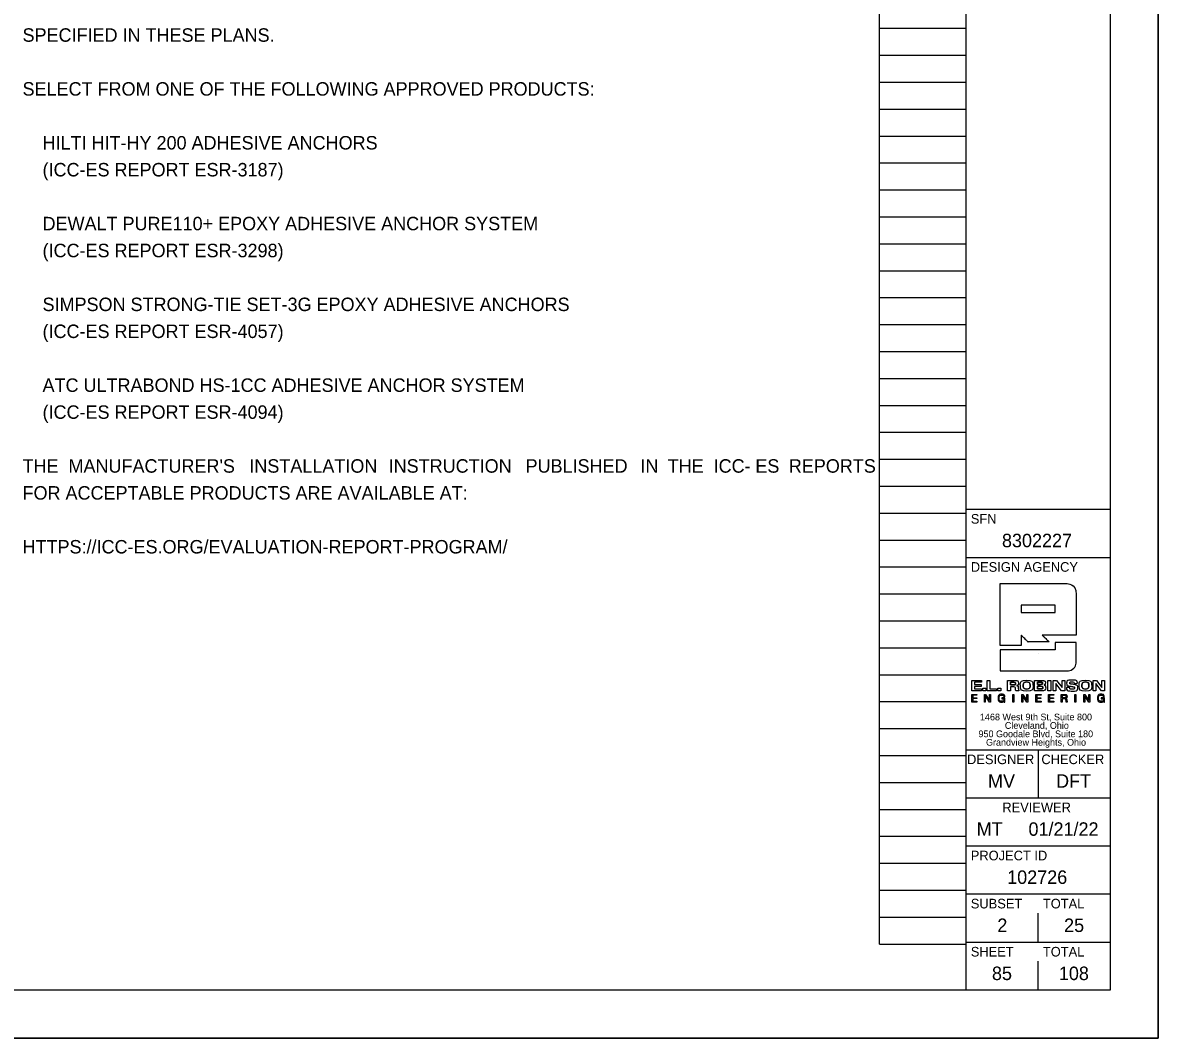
# Model space of a CAD drawing. Extents: x 0 to 34, y 0 to 22.
# Drawn here: x 22.19 to 34, y 0 to 10.56 of the extents above; entities that cross this region are included whole.
import ezdxf

# ---------------------------------------------------------------- set-up
doc = ezdxf.new("R2010")
doc.units = 0
for name, color, linetype in [('SC_Scratch1', 7, 'Continuous'), ('SH_Border', 7, 'Continuous'), ('SH_Cut_Line', 7, 'Continuous'), ('SH_Data', 7, 'Continuous'), ('SH_Text', 7, 'Continuous')]:
    doc.layers.add(name, color=color, linetype=linetype)

msp = doc.modelspace()

# ---------------------------------------------------------------- linework, layer by layer
at = {"layer": 'SC_Scratch1'}
for p, q in [((31.1, 0.98), (31.1, 21.14)), ((32, 0.98), (32, 21.14)), ((31.1, 10.5), (32, 10.5)), ((31.1, 10.22), (32, 10.22)), ((31.1, 9.94), (32, 9.94)), ((31.1, 9.66), (32, 9.66)), ((31.1, 9.38), (32, 9.38)), ((31.1, 9.1), (32, 9.1)), ((31.1, 8.82), (32, 8.82)), ((31.1, 8.54), (32, 8.54)), ((31.1, 8.26), (32, 8.26)), ((31.1, 7.98), (32, 7.98)), ((31.1, 7.7), (32, 7.7)), ((31.1, 7.42), (32, 7.42)), ((31.1, 7.14), (32, 7.14)), ((31.1, 6.86), (32, 6.86)), ((31.1, 6.58), (32, 6.58)), ((31.1, 6.3), (32, 6.3)), ((31.1, 6.02), (32, 6.02)), ((31.1, 5.74), (32, 5.74)), ((31.1, 5.46), (32, 5.46)), ((31.1, 5.18), (32, 5.18)), ((31.1, 4.9), (32, 4.9)), ((31.1, 4.62), (32, 4.62)), ((31.1, 4.34), (32, 4.34)), ((31.1, 4.06), (32, 4.06)), ((31.1, 3.78), (32, 3.78)), ((31.1, 3.5), (32, 3.5)), ((31.1, 3.22), (32, 3.22)), ((31.1, 2.94), (32, 2.94)), ((31.1, 2.66), (32, 2.66)), ((31.1, 2.38), (32, 2.38)), ((31.1, 2.1), (32, 2.1)), ((31.1, 1.82), (32, 1.82)), ((31.1, 1.54), (32, 1.54)), ((31.1, 1.26), (32, 1.26)), ((31.1, 0.98), (32, 0.98))]:
    msp.add_line(p, q, dxfattribs=at)
msp.add_lwpolyline([(0, 22), (34, 22), (34, 0), (0, 0)], close=True, dxfattribs=at)
at = {"layer": 'SH_Border'}
for p, q in [((32, 0.5), (32, 21.5)), ((32, 5.5), (33.5, 5.5)), ((32, 5), (33.5, 5)), ((32, 3), (33.5, 3)), ((32.75, 3), (32.75, 2.5)), ((32, 2.5), (33.5, 2.5)), ((32, 2), (33.5, 2)), ((32, 1.5), (33.5, 1.5)), ((32, 1), (33.5, 1))]:
    msp.add_line(p, q, dxfattribs=at)
msp.add_lwpolyline([(1.5, 21.5), (33.5, 21.5), (33.5, 0.5), (1.5, 0.5)], close=True, dxfattribs=at)
at = {"layer": 'SH_Cut_Line'}
msp.add_lwpolyline([(0, 0), (34, 0), (34, 22), (0, 22)], close=True, dxfattribs=at)
at = {"layer": 'SH_Data'}
for p, q in [((32.929, 4.503), (32.574, 4.503)), ((32.574, 4.503), (32.574, 4.425)), ((32.929, 4.425), (32.929, 4.503)), ((32.574, 4.425), (32.929, 4.425)), ((32.75, 4), (32.75, 4)), ((32.463, 3.701), (32.463, 3.673)), ((32.743, 3.702), (32.743, 3.678)), ((32.743, 3.659), (32.743, 3.633)), ((33.001, 3.566), (33.001, 3.539)), ((33.001, 3.539), (33.023, 3.539)), ((32.75, 1), (32.75, 1.3)), ((32.75, 0.5), (32.75, 0.8)), ((32.375, 0.675), (32.375, 0.675))]:
    msp.add_line(p, q, dxfattribs=at)
for points in [[(32.06, 3.721), (32.161, 3.721), (32.161, 3.701), (32.089, 3.701), (32.089, 3.678), (32.158, 3.678), (32.158, 3.658), (32.089, 3.658), (32.089, 3.633), (32.162, 3.633), (32.162, 3.613), (32.06, 3.613), (32.06, 3.721)], [(32.22, 3.721), (32.249, 3.721), (32.249, 3.634), (32.316, 3.634), (32.316, 3.613), (32.22, 3.613), (32.22, 3.721)], [(32.851, 3.721), (32.881, 3.721), (32.881, 3.613), (32.851, 3.613), (32.851, 3.721)], [(32.999, 3.721), (33.027, 3.721), (33.027, 3.613), (32.995, 3.613), (32.936, 3.689), (32.936, 3.689), (32.936, 3.613), (32.907, 3.613), (32.907, 3.721), (32.941, 3.721), (32.999, 3.646), (32.999, 3.646), (32.999, 3.721)], [(33.413, 3.721), (33.442, 3.721), (33.442, 3.613), (33.41, 3.613), (33.35, 3.689), (33.35, 3.689), (33.35, 3.613), (33.321, 3.613), (33.321, 3.721), (33.356, 3.721), (33.413, 3.646), (33.413, 3.646), (33.413, 3.721)], [(32.059, 3.575), (32.114, 3.575), (32.114, 3.566), (32.07, 3.566), (32.07, 3.541), (32.111, 3.541), (32.111, 3.532), (32.07, 3.532), (32.07, 3.505), (32.114, 3.505), (32.114, 3.496), (32.059, 3.496), (32.059, 3.575)], [(32.175, 3.639), (32.205, 3.639), (32.205, 3.613), (32.175, 3.613), (32.175, 3.639)], [(32.191, 3.575), (32.203, 3.575), (32.244, 3.511), (32.244, 3.511), (32.244, 3.575), (32.254, 3.575), (32.254, 3.496), (32.243, 3.496), (32.202, 3.559), (32.201, 3.559), (32.201, 3.496), (32.191, 3.496), (32.191, 3.575)], [(32.331, 3.639), (32.361, 3.639), (32.361, 3.613), (32.331, 3.613), (32.331, 3.639)], [(32.487, 3.575), (32.498, 3.575), (32.498, 3.496), (32.487, 3.496), (32.487, 3.575)], [(32.581, 3.575), (32.592, 3.575), (32.633, 3.511), (32.633, 3.511), (32.633, 3.575), (32.643, 3.575), (32.643, 3.496), (32.632, 3.496), (32.591, 3.559), (32.591, 3.559), (32.591, 3.496), (32.581, 3.496), (32.581, 3.575)], [(32.726, 3.575), (32.781, 3.575), (32.781, 3.566), (32.737, 3.566), (32.737, 3.541), (32.778, 3.541), (32.778, 3.532), (32.737, 3.532), (32.737, 3.505), (32.781, 3.505), (32.781, 3.496), (32.726, 3.496), (32.726, 3.575)], [(32.859, 3.575), (32.913, 3.575), (32.913, 3.566), (32.869, 3.566), (32.869, 3.541), (32.91, 3.541), (32.91, 3.532), (32.869, 3.532), (32.869, 3.505), (32.913, 3.505), (32.913, 3.496), (32.859, 3.496), (32.859, 3.575)], [(33.133, 3.575), (33.143, 3.575), (33.143, 3.496), (33.133, 3.496), (33.133, 3.575)], [(33.226, 3.575), (33.237, 3.575), (33.279, 3.511), (33.279, 3.511), (33.279, 3.575), (33.289, 3.575), (33.289, 3.496), (33.277, 3.496), (33.236, 3.559), (33.236, 3.559), (33.236, 3.496), (33.226, 3.496), (33.226, 3.575)]]:
    msp.add_lwpolyline(points, dxfattribs=at)
for points, degree in [([(32.356, 4.083), (32.356, 4.086), (32.356, 4.724), (32.356, 4.727)], 2), ([(32.356, 4.727), (32.36, 4.727), (33.03, 4.727), (33.034, 4.727), (33.096, 4.727), (33.147, 4.677), (33.147, 4.614)], 3), ([(33.147, 4.614), (33.147, 4.612), (33.147, 4.194), (33.147, 4.192)], 2), ([(32.645, 4.121), (32.645, 4.121), (32.574, 4.191), (32.574, 4.192)], 2), ([(32.574, 4.192), (32.574, 4.191), (32.574, 4.083), (32.574, 4.083)], 2), ([(33.147, 4.192), (33.145, 4.192), (32.795, 4.192), (32.793, 4.192)], 2), ([(32.793, 4.192), (32.793, 4.191), (32.866, 4.121), (32.866, 4.121)], 2), ([(32.929, 4.115), (32.929, 4.115), (33.147, 4.115), (33.147, 4.115), (33.147, 4.115), (33.147, 3.933), (33.147, 3.933), (33.147, 3.87), (33.096, 3.82), (33.034, 3.82), (33.034, 3.82), (32.356, 3.82), (32.356, 3.82), (32.356, 3.82), (32.356, 4.037), (32.356, 4.037), (32.356, 4.037), (32.929, 4.037), (32.929, 4.037), (32.929, 4.037), (32.929, 4.115), (32.929, 4.115)], 3), ([(32.574, 4.083), (32.573, 4.083), (32.357, 4.083), (32.356, 4.083)], 2), ([(32.866, 4.121), (32.865, 4.121), (32.646, 4.121), (32.645, 4.121)], 2), ([(32.433, 3.613), (32.433, 3.613), (32.433, 3.721), (32.433, 3.721)], 2), ([(32.433, 3.721), (32.433, 3.721), (32.512, 3.721), (32.512, 3.721), (32.542, 3.721), (32.545, 3.703), (32.546, 3.692)], 3), ([(32.463, 3.673), (32.463, 3.673), (32.502, 3.673), (32.502, 3.673), (32.508, 3.673), (32.516, 3.677), (32.516, 3.687), (32.516, 3.698), (32.507, 3.701), (32.5, 3.701), (32.5, 3.701), (32.463, 3.701), (32.463, 3.701), (32.463, 3.701), (32.463, 3.673), (32.463, 3.673)], 3), ([(32.463, 3.673), (32.476, 3.673), (32.489, 3.673), (32.508, 3.673), (32.516, 3.677), (32.516, 3.698), (32.507, 3.701), (32.488, 3.701), (32.475, 3.701), (32.463, 3.701)], 3), ([(32.546, 3.692), (32.544, 3.679), (32.542, 3.67), (32.53, 3.666)], 2), ([(32.53, 3.666), (32.53, 3.666), (32.53, 3.665), (32.53, 3.665)], 2), ([(32.53, 3.665), (32.543, 3.663), (32.544, 3.647), (32.544, 3.636)], 2), ([(32.631, 3.61), (32.573, 3.61), (32.567, 3.645), (32.565, 3.667), (32.564, 3.69), (32.573, 3.724), (32.631, 3.724)], 3), ([(32.631, 3.63), (32.658, 3.63), (32.667, 3.65), (32.667, 3.667), (32.667, 3.684), (32.658, 3.704), (32.631, 3.704), (32.604, 3.704), (32.595, 3.684), (32.595, 3.667), (32.595, 3.65), (32.604, 3.63), (32.631, 3.63)], 3), ([(32.631, 3.704), (32.604, 3.704), (32.595, 3.684), (32.595, 3.667), (32.595, 3.65), (32.604, 3.63), (32.631, 3.63)], 3), ([(32.631, 3.724), (32.69, 3.724), (32.695, 3.689), (32.697, 3.667), (32.699, 3.644), (32.69, 3.61), (32.631, 3.61)], 3), ([(32.631, 3.63), (32.658, 3.63), (32.667, 3.65), (32.667, 3.667), (32.667, 3.684), (32.658, 3.704), (32.631, 3.704)], 3), ([(32.714, 3.613), (32.714, 3.613), (32.714, 3.721), (32.714, 3.721)], 2), ([(32.714, 3.721), (32.714, 3.721), (32.795, 3.721), (32.795, 3.721)], 2), ([(32.743, 3.678), (32.743, 3.678), (32.784, 3.678), (32.784, 3.678), (32.791, 3.678), (32.796, 3.682), (32.796, 3.69), (32.796, 3.697), (32.793, 3.702), (32.78, 3.702), (32.78, 3.702), (32.743, 3.702), (32.743, 3.702), (32.743, 3.702), (32.743, 3.678), (32.743, 3.678)], 3), ([(32.743, 3.678), (32.757, 3.678), (32.771, 3.678), (32.791, 3.681), (32.791, 3.683), (32.792, 3.697), (32.793, 3.702), (32.768, 3.702), (32.756, 3.702), (32.743, 3.702)], 3), ([(32.795, 3.721), (32.81, 3.718), (32.826, 3.714), (32.826, 3.694)], 2), ([(32.826, 3.694), (32.824, 3.686), (32.822, 3.675), (32.812, 3.672)], 2), ([(32.812, 3.672), (32.812, 3.672), (32.812, 3.672), (32.812, 3.672)], 2), ([(32.812, 3.672), (32.824, 3.67), (32.827, 3.656), (32.829, 3.645)], 2), ([(33.126, 3.69), (33.124, 3.704), (33.111, 3.706), (33.099, 3.706), (33.087, 3.706), (33.079, 3.7), (33.079, 3.693), (33.079, 3.687), (33.084, 3.684), (33.091, 3.683), (33.091, 3.683), (33.128, 3.677), (33.128, 3.677), (33.148, 3.673), (33.163, 3.666), (33.163, 3.646), (33.163, 3.626), (33.149, 3.61), (33.107, 3.61), (33.08, 3.61), (33.046, 3.613), (33.045, 3.647), (33.045, 3.647), (33.079, 3.647), (33.079, 3.647), (33.079, 3.632), (33.094, 3.629), (33.107, 3.629), (33.121, 3.629), (33.13, 3.634), (33.13, 3.643), (33.13, 3.651), (33.123, 3.654), (33.112, 3.655), (33.112, 3.655), (33.085, 3.66), (33.085, 3.66), (33.066, 3.662), (33.047, 3.668), (33.047, 3.69), (33.047, 3.715), (33.067, 3.724), (33.101, 3.724), (33.124, 3.724), (33.157, 3.721), (33.159, 3.69), (33.159, 3.69), (33.126, 3.69), (33.126, 3.69)], 3), ([(33.242, 3.61), (33.183, 3.61), (33.178, 3.645), (33.176, 3.667), (33.174, 3.69), (33.183, 3.724), (33.242, 3.724)], 3), ([(33.242, 3.63), (33.269, 3.63), (33.278, 3.65), (33.278, 3.667), (33.278, 3.684), (33.269, 3.704), (33.242, 3.704), (33.215, 3.704), (33.205, 3.684), (33.205, 3.667), (33.205, 3.65), (33.215, 3.63), (33.242, 3.63)], 3), ([(33.242, 3.704), (33.215, 3.704), (33.205, 3.684), (33.205, 3.667), (33.205, 3.65), (33.215, 3.63), (33.242, 3.63)], 3), ([(33.242, 3.724), (33.3, 3.724), (33.306, 3.689), (33.308, 3.667), (33.309, 3.644), (33.3, 3.61), (33.242, 3.61)], 3), ([(33.242, 3.63), (33.269, 3.63), (33.278, 3.65), (33.278, 3.667), (33.278, 3.684), (33.269, 3.704), (33.242, 3.704)], 3), ([(32.396, 3.506), (32.39, 3.498), (32.38, 3.494), (32.37, 3.494), (32.347, 3.494), (32.333, 3.514), (32.333, 3.534), (32.333, 3.557), (32.346, 3.577), (32.37, 3.577), (32.388, 3.577), (32.401, 3.569), (32.404, 3.551), (32.404, 3.551), (32.394, 3.551), (32.394, 3.551), (32.392, 3.562), (32.382, 3.568), (32.37, 3.568), (32.351, 3.568), (32.344, 3.551), (32.344, 3.534), (32.344, 3.518), (32.353, 3.503), (32.37, 3.503), (32.387, 3.503), (32.396, 3.515), (32.396, 3.529), (32.396, 3.529), (32.371, 3.529), (32.371, 3.529), (32.371, 3.529), (32.371, 3.538), (32.371, 3.538), (32.371, 3.538), (32.405, 3.538), (32.405, 3.538), (32.405, 3.538), (32.405, 3.496), (32.405, 3.496), (32.405, 3.496), (32.398, 3.496), (32.398, 3.496), (32.398, 3.496), (32.396, 3.506), (32.396, 3.506)], 3), ([(32.463, 3.613), (32.462, 3.613), (32.433, 3.613), (32.433, 3.613)], 2), ([(32.499, 3.653), (32.499, 3.653), (32.463, 3.653), (32.463, 3.653)], 2), ([(32.463, 3.653), (32.463, 3.652), (32.463, 3.613), (32.463, 3.613)], 2), ([(32.518, 3.613), (32.516, 3.618), (32.516, 3.622), (32.516, 3.634), (32.515, 3.649), (32.508, 3.65), (32.499, 3.653)], 3), ([(32.55, 3.613), (32.55, 3.613), (32.518, 3.613), (32.518, 3.613)], 2), ([(32.544, 3.636), (32.544, 3.631), (32.548, 3.619), (32.55, 3.613)], 2), ([(32.829, 3.645), (32.827, 3.632), (32.824, 3.613), (32.791, 3.613), (32.791, 3.613), (32.714, 3.613), (32.714, 3.613)], 3), ([(32.743, 3.633), (32.743, 3.633), (32.787, 3.633), (32.787, 3.633), (32.796, 3.633), (32.8, 3.639), (32.8, 3.646), (32.8, 3.655), (32.794, 3.659), (32.784, 3.659), (32.784, 3.659), (32.743, 3.659), (32.743, 3.659), (32.743, 3.659), (32.743, 3.633), (32.743, 3.633)], 3), ([(32.743, 3.633), (32.758, 3.633), (32.772, 3.633), (32.796, 3.633), (32.8, 3.639), (32.8, 3.655), (32.794, 3.659), (32.77, 3.659), (32.757, 3.659), (32.743, 3.659)], 3), ([(32.991, 3.575), (32.991, 3.575), (33.027, 3.575), (33.028, 3.575), (33.042, 3.575), (33.051, 3.567), (33.051, 3.554)], 3), ([(32.991, 3.496), (32.991, 3.497), (32.991, 3.574), (32.991, 3.575)], 2), ([(33.023, 3.539), (33.033, 3.539), (33.041, 3.541), (33.041, 3.552), (33.041, 3.56), (33.037, 3.566), (33.027, 3.566), (33.027, 3.566), (33.001, 3.566), (33.001, 3.566), (33.001, 3.566), (33.001, 3.539), (33.001, 3.539), (33.001, 3.539), (33.023, 3.539), (33.023, 3.539)], 3), ([(33.023, 3.539), (33.033, 3.539), (33.041, 3.541), (33.041, 3.56), (33.037, 3.566), (33.018, 3.566), (33.01, 3.566), (33.001, 3.566)], 3), ([(33.051, 3.554), (33.049, 3.545), (33.047, 3.537), (33.038, 3.534)], 2), ([(33.43, 3.506), (33.424, 3.498), (33.414, 3.494), (33.405, 3.494), (33.382, 3.494), (33.368, 3.514), (33.368, 3.534), (33.368, 3.557), (33.38, 3.577), (33.405, 3.577), (33.422, 3.577), (33.436, 3.569), (33.439, 3.551), (33.439, 3.551), (33.429, 3.551), (33.429, 3.551), (33.426, 3.562), (33.417, 3.568), (33.405, 3.568), (33.386, 3.568), (33.378, 3.551), (33.378, 3.534), (33.378, 3.518), (33.388, 3.503), (33.405, 3.503), (33.421, 3.503), (33.431, 3.515), (33.43, 3.529), (33.43, 3.529), (33.405, 3.529), (33.405, 3.529), (33.405, 3.529), (33.405, 3.538), (33.405, 3.538), (33.405, 3.538), (33.44, 3.538), (33.44, 3.538), (33.44, 3.538), (33.44, 3.496), (33.44, 3.496), (33.44, 3.496), (33.433, 3.496), (33.433, 3.496), (33.433, 3.496), (33.43, 3.506), (33.43, 3.506)], 3), ([(33.001, 3.496), (33.001, 3.496), (32.991, 3.496), (32.991, 3.496)], 2), ([(33.04, 3.516), (33.038, 3.523), (33.037, 3.53), (33.027, 3.53), (33.027, 3.53), (33.001, 3.53), (33.001, 3.53)], 3), ([(33.001, 3.53), (33.001, 3.53), (33.001, 3.496), (33.001, 3.496)], 2), ([(33.038, 3.534), (33.038, 3.534), (33.038, 3.534), (33.038, 3.534)], 2), ([(33.038, 3.534), (33.044, 3.529), (33.047, 3.525), (33.048, 3.518)], 2), ([(33.043, 3.496), (33.042, 3.5), (33.041, 3.508), (33.04, 3.516)], 2), ([(33.054, 3.496), (33.054, 3.496), (33.043, 3.496), (33.043, 3.496)], 2), ([(33.048, 3.518), (33.049, 3.51), (33.052, 3.502), (33.054, 3.496)], 2)]:
    msp.add_open_spline(points, degree=degree, dxfattribs=at)

# ---------------------------------------------------------------- texts
for s, height, p in [('SFN', 0.1, (32.05, 5.35)), ('8302227', 0.14, (32.374, 5.105)), ('DESIGN AGENCY', 0.1, (32.05, 4.85)), ('1468 West 9th St, Suite 800', 0.07, (32.145, 3.305)), ('950 Goodale Blvd, Suite 180', 0.07, (32.13, 3.13)), ('Cleveland, Ohio', 0.07, (32.404, 3.217)), ('Grandview Heights, Ohio', 0.07, (32.208, 3.042)), ('DESIGNER', 0.1, (32.011, 2.85)), ('CHECKER', 0.1, (32.784, 2.85)), ('MV', 0.14, (32.229, 2.605)), ('DFT', 0.14, (32.937, 2.605)), ('REVIEWER', 0.1, (32.378, 2.35)), ('MT', 0.14, (32.111, 2.105)), ('01/21/22', 0.14, (32.65, 2.105)), ('PROJECT ID', 0.1, (32.05, 1.85)), ('102726', 0.14, (32.428, 1.605)), ('SUBSET', 0.1, (32.05, 1.35)), ('TOTAL', 0.1, (32.8, 1.35)), ('2', 0.14, (32.326, 1.105)), ('25', 0.14, (33.02, 1.105)), ('SHEET', 0.1, (32.05, 0.85)), ('TOTAL', 0.1, (32.8, 0.85)), ('85', 0.14, (32.27, 0.605)), ('108', 0.14, (32.966, 0.605))]:
    msp.add_text(s, height=height, dxfattribs=at).set_placement(p)
at = {"layer": 'SH_Text'}
for s, p in [('SPECIFIED IN THESE PLANS.', (22.187, 10.36)), ('SELECT FROM ONE OF THE FOLLOWING APPROVED PRODUCTS:   ', (22.187, 9.8)), ('    HILTI HIT-HY 200 ADHESIVE ANCHORS ', (22.187, 9.24)), ('    (ICC-ES REPORT ESR-3187) ', (22.187, 8.96)), ('    DEWALT PURE110+ EPOXY ADHESIVE ANCHOR SYSTEM  ', (22.187, 8.4)), ('    (ICC-ES REPORT ESR-3298) ', (22.187, 8.12)), ('    SIMPSON STRONG-TIE SET-3G EPOXY ADHESIVE ANCHORS   ', (22.187, 7.56)), ('    (ICC-ES REPORT ESR-4057) ', (22.187, 7.28)), ('    ATC ULTRABOND HS-1CC ADHESIVE ANCHOR SYSTEM   ', (22.187, 6.72)), ('    (ICC-ES REPORT ESR-4094) ', (22.187, 6.44)), ('THE ', (22.187, 5.88)), ("MANUFACTURER'S ", (22.665, 5.88)), ('INSTALLATION ', (24.546, 5.88)), ('INSTRUCTION ', (25.995, 5.88)), ('PUBLISHED ', (27.419, 5.88)), ('IN ', (28.614, 5.88)), ('THE ', (28.897, 5.88)), ('ICC-', (29.375, 5.88)), ('ES ', (29.809, 5.88)), ('REPORTS ', (30.157, 5.88)), ('FOR ACCEPTABLE PRODUCTS ARE AVAILABLE AT: ', (22.187, 5.6)), ('HTTPS://ICC-ES.ORG/EVALUATION-REPORT-PROGRAM/', (22.187, 5.04))]:
    msp.add_text(s, height=0.14, dxfattribs=at).set_placement(p)

doc.saveas('drawing.dxf')
